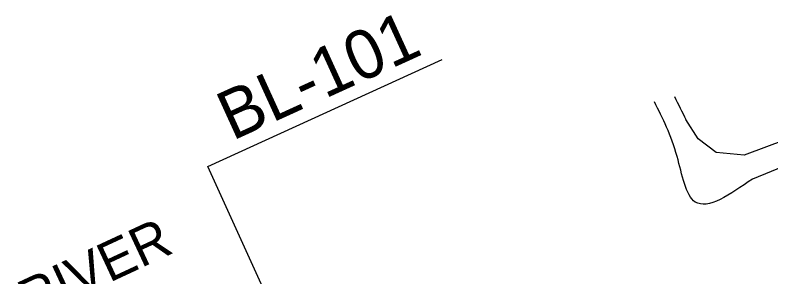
# Model space of a CAD drawing. Extents: x 2243531 to 2252747, y 658714 to 667210.
# Drawn here: x 2248974 to 2249747, y 663785 to 664052 of the extents above; entities that cross this region are included whole.
import ezdxf

# ---------------------------------------------------------------- set-up
doc = ezdxf.new("R2010")
doc.units = 0
for name, color, linetype in [('CTL NGS Horizontal CELL', 7, 'Continuous'), ('CTL Supplemental Horizontal and Vertical Text', 7, 'Continuous'), ('Exist Hydro Stream or Body of Water Text', 7, 'Continuous'), ('Exist Roads EOP', 7, 'Continuous')]:
    doc.layers.add(name, color=color, linetype=linetype)

msp = doc.modelspace()

# ---------------------------------------------------------------- linework, layer by layer
at = {"layer": 'CTL NGS Horizontal CELL'}
for p, q in [((2249171.33, 663897.43), (2249410.86, 664007.05)), ((2249355.99, 663492.2), (2249171.33, 663897.43))]:
    msp.add_line(p, q, dxfattribs=at)
at = {"layer": 'Exist Roads EOP'}
for points in [[(2249821.42, 663952.01), (2249817.14, 663950.24), (2249762.5, 663925.2), (2249719.52, 663909.32), (2249690.94, 663911.99), (2249672.57, 663925.89), (2249660.16, 663945.61)], [(2249821.42, 663952.01), (2249817.14, 663950.24), (2249762.5, 663925.2), (2249719.52, 663909.32), (2249690.94, 663911.99), (2249672.57, 663925.89), (2249660.16, 663945.61)], [(2249829.5, 663929.68), (2249828.55, 663928.96), (2249772.03, 663902.84), (2249728.05, 663884.69)], [(2249829.5, 663929.68), (2249828.55, 663928.96), (2249772.03, 663902.84), (2249728.05, 663884.69)]]:
    msp.add_lwpolyline(points, dxfattribs=at)
msp.add_ellipse((2250151.19, 664206.99), major_axis=(213.02, -532.81), ratio=0.969065, start_param=4.771919, end_param=4.817873, dxfattribs=at)
msp.add_ellipse((2250151.19, 664206.99), major_axis=(213.02, -532.81), ratio=0.969065, start_param=4.771919, end_param=4.817873, dxfattribs=at)
msp.add_spline([(2249728.05, 663884.69), (2249669.68, 663861.2), (2249651.13, 663907.73), (2249627.88, 663963.78)], degree=3, dxfattribs=at)
msp.add_spline([(2249728.05, 663884.69), (2249669.68, 663861.2), (2249651.13, 663907.73), (2249627.88, 663963.78)], degree=3, dxfattribs=at)

# ---------------------------------------------------------------- texts
at = {"layer": 'CTL Supplemental Horizontal and Vertical Text'}
msp.add_text('BL-101', height=49.999, rotation=24.49794, dxfattribs=at).set_placement((2249196.36, 663923.54))
at = {"layer": 'Exist Hydro Stream or Body of Water Text'}
msp.add_text('LITTLE RIVER', height=39.9995, rotation=24.98751, dxfattribs=at).set_placement((2248817.41, 663660.43))

doc.saveas('drawing.dxf')
